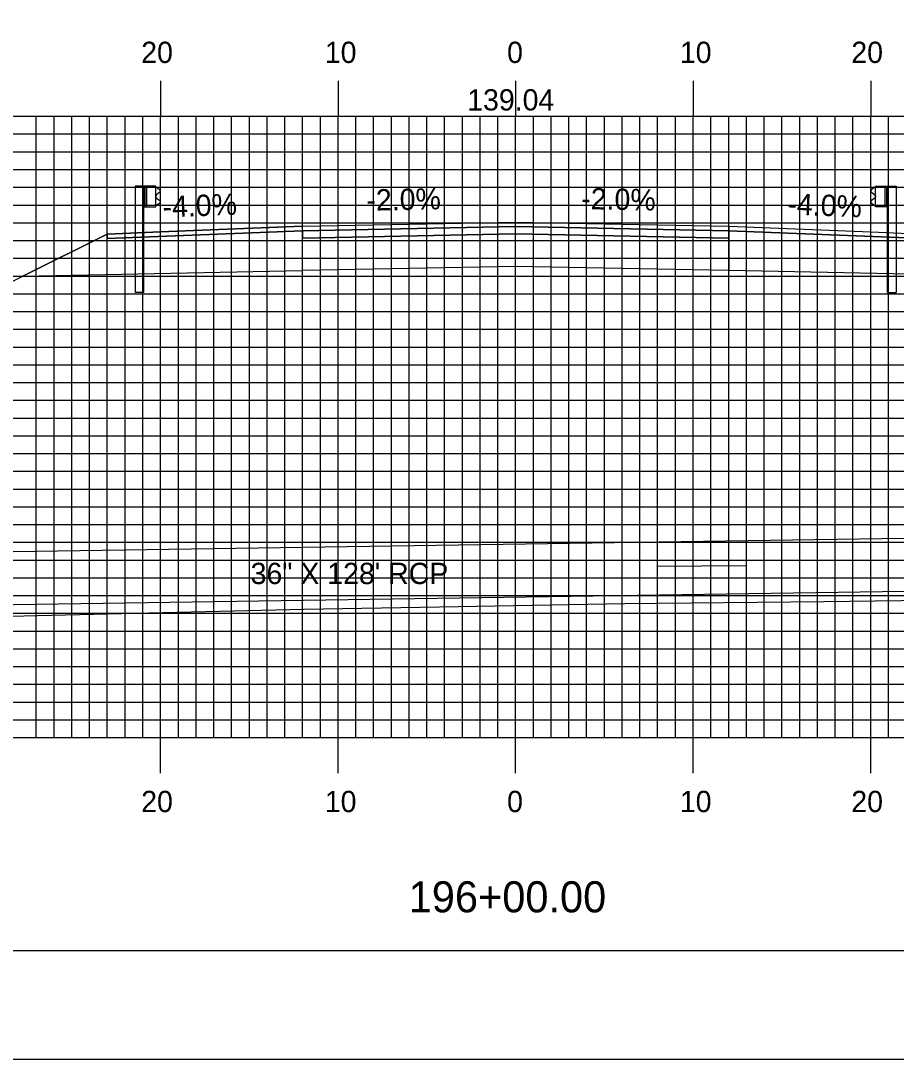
# Model space of a CAD drawing. Extents: x 1789730 to 1790074, y 442591 to 442811.
# Drawn here: x 1789868.3 to 1789917.6, y 442590.5 to 442649 of the extents above; entities that cross this region are included whole.
import ezdxf

# ---------------------------------------------------------------- set-up
doc = ezdxf.new("R2010")
doc.units = 0
for name, color, linetype in [('ANNOTATION', 7, 'Continuous'), ('BORDER', 7, 'Continuous'), ('D_Drainage_Culvert', 7, 'Continuous'), ('D_Drainage_Text', 7, 'Continuous'), ('D_Guardrail_Beam_Lt', 7, 'Continuous'), ('D_Guardrail_Beam_Rt', 7, 'Continuous'), ('D_Roadway_Centerline', 7, 'Continuous'), ('D_Roadway_Centerline_Text', 7, 'Continuous'), ('D_Roadway_Edge_Shoulder', 7, 'Continuous'), ('D_Roadway_Edge_TW', 7, 'Continuous'), ('D_Roadway_Pavement', 7, 'Continuous'), ('D_Roadway_SlopeLines', 7, 'Continuous'), ('D_Roadway_SubGrade', 7, 'Continuous'), ('H_V ANNOTATION', 7, 'Continuous'), ('MAJOR', 7, 'Continuous'), ('MINOR', 7, 'Continuous'), ('PLOT BOUNDARY', 7, 'Continuous'), ('S_Roadway_Centerline', 7, 'Continuous')]:
    doc.layers.add(name, color=color, linetype=linetype)

msp = doc.modelspace()

# ---------------------------------------------------------------- linework, layer by layer
at = {"layer": 'BORDER'}
msp.add_lwpolyline([(1789746.583, 442596.665), (1790066.583, 442596.665), (1790066.583, 442806.665), (1789746.583, 442806.665)], close=True, dxfattribs=at)
at = {"layer": 'D_Drainage_Culvert'}
msp.add_line((1789909.145, 442618.335), (1789904.158, 442618.294), dxfattribs=at)
msp.add_lwpolyline([(1789830.264, 442615.576), (1789830.219, 442618.576), (1789958.204, 442620.494), (1789958.249, 442617.494)], close=True, dxfattribs=at)
at = {"layer": 'D_Guardrail_Beam_Lt'}
for p, q in [((1789874.754, 442639.731), (1789874.754, 442633.731)), ((1789875.224, 442639.731), (1789874.754, 442639.731)), ((1789875.912, 442639.731), (1789875.224, 442639.731)), ((1789875.224, 442639.731), (1789875.224, 442638.564)), ((1789875.287, 442639.731), (1789875.287, 442638.564)), ((1789875.391, 442639.731), (1789875.391, 442638.564)), ((1789875.912, 442638.564), (1789875.912, 442639.731)), ((1789875.912, 442639.647), (1789875.986, 442639.633)), ((1789875.916, 442639.183), (1789875.916, 442639.112)), ((1789876.145, 442639.383), (1789875.95, 442639.247)), ((1789876.002, 442639.626), (1789876.145, 442639.526)), ((1789875.224, 442638.564), (1789875.912, 442638.564)), ((1789875.245, 442633.731), (1789875.245, 442638.564)), ((1789875.986, 442638.662), (1789875.912, 442638.647)), ((1789875.95, 442639.048), (1789876.145, 442638.912)), ((1789876.145, 442638.769), (1789876.002, 442638.669)), ((1789875.245, 442633.731), (1789874.754, 442633.731))]:
    msp.add_line(p, q, dxfattribs=at)
for centre, major_axis, start_param, end_param in [((1789875.995, 442639.183), (-0.0789, 0), 5.323254, 6.283185), ((1789875.995, 442639.112), (-0.0789, 0), 6.283185, 7.243116), ((1789875.978, 442639.592), (0.0417, 0), 0.959931, 1.376053), ((1789876.095, 442639.455), (0.0877, 0), 5.323254, 7.243116), ((1789875.978, 442638.703), (0.0417, 0), 4.907132, 5.323254), ((1789876.095, 442638.84), (0.0877, 0), 5.323254, 7.243116)]:
    msp.add_ellipse(centre, major_axis=major_axis, ratio=0.995501, start_param=start_param, end_param=end_param, dxfattribs=at)
at = {"layer": 'D_Guardrail_Beam_Rt'}
for p, q in [((1789916.454, 442639.647), (1789916.379, 442639.633)), ((1789916.454, 442639.731), (1789917.141, 442639.731)), ((1789916.454, 442638.564), (1789916.454, 442639.731)), ((1789916.974, 442639.731), (1789916.974, 442638.564)), ((1789917.079, 442639.731), (1789917.079, 442638.564)), ((1789917.141, 442639.731), (1789917.612, 442639.731)), ((1789917.141, 442639.731), (1789917.141, 442638.564)), ((1789917.612, 442639.731), (1789917.612, 442633.731)), ((1789916.364, 442639.626), (1789916.22, 442639.526)), ((1789916.22, 442639.383), (1789916.415, 442639.247)), ((1789916.449, 442639.183), (1789916.449, 442639.112)), ((1789916.415, 442639.048), (1789916.22, 442638.912)), ((1789916.22, 442638.769), (1789916.364, 442638.669)), ((1789916.379, 442638.662), (1789916.454, 442638.647)), ((1789917.141, 442638.564), (1789916.454, 442638.564)), ((1789917.12, 442633.731), (1789917.12, 442638.564)), ((1789917.12, 442633.731), (1789917.612, 442633.731))]:
    msp.add_line(p, q, dxfattribs=at)
for centre, major_axis, start_param, end_param in [((1789916.27, 442639.455), (-0.0877, 0), 5.323254, 7.243116), ((1789916.387, 442639.592), (-0.0417, 0), 4.907132, 5.323254), ((1789916.37, 442639.183), (0.0789, 0), 0, 0.959931), ((1789916.37, 442639.112), (0.0789, 0), 5.323254, 6.283185), ((1789916.27, 442638.84), (-0.0877, 0), 5.323254, 7.243116), ((1789916.387, 442638.703), (-0.0417, 0), 0.959931, 1.376053)]:
    msp.add_ellipse(centre, major_axis=major_axis, ratio=0.995501, start_param=start_param, end_param=end_param, dxfattribs=at)
at = {"layer": 'D_Roadway_Centerline'}
msp.add_lwpolyline([(1789830.28, 442615.576), (1789868.433, 442634.652), (1789873.183, 442637.027), (1789876.183, 442637.147), (1789884.183, 442637.467), (1789896.183, 442637.707), (1789908.183, 442637.467), (1789916.183, 442637.147), (1789919.183, 442637.027), (1789923.933, 442634.652), (1789958.249, 442617.494)], dxfattribs=at)
at = {"layer": 'D_Roadway_Edge_Shoulder'}
for points in [[(1789884.183, 442637.467), (1789876.183, 442637.147), (1789876.183, 442637.147), (1789873.183, 442637.027), (1789873.183, 442636.777), (1789884.183, 442637.217)], [(1789908.183, 442637.467), (1789916.183, 442637.147), (1789916.183, 442637.147), (1789919.183, 442637.027), (1789919.183, 442636.777), (1789908.183, 442637.217)]]:
    msp.add_lwpolyline(points, close=True, dxfattribs=at)
at = {"layer": 'D_Roadway_Edge_TW'}
msp.add_lwpolyline([(1789884.183, 442637.217), (1789884.183, 442637.467), (1789896.183, 442637.707), (1789908.183, 442637.467), (1789908.183, 442637.217), (1789896.183, 442637.457)], close=True, dxfattribs=at)
at = {"layer": 'D_Roadway_Pavement'}
msp.add_lwpolyline([(1789884.183, 442636.801), (1789884.183, 442637.217), (1789896.183, 442637.457), (1789908.183, 442637.217), (1789908.183, 442636.801), (1789896.183, 442637.041)], close=True, dxfattribs=at)
for points in [[(1789884.183, 442637.217), (1789884.183, 442636.801)], [(1789908.183, 442637.217), (1789908.183, 442636.801)]]:
    msp.add_lwpolyline(points, dxfattribs=at)
at = {"layer": 'D_Roadway_SlopeLines'}
msp.add_lwpolyline([(1789873.183, 442637.027), (1789830.28, 442615.576)], dxfattribs=at)
at = {"layer": 'D_Roadway_SubGrade'}
for points in [[(1789884.183, 442636.801), (1789884.183, 442637.217), (1789873.183, 442636.777), (1789873.183, 442637.027), (1789868.433, 442634.652), (1789884.183, 442634.967)], [(1789884.183, 442634.967), (1789884.183, 442637.217), (1789884.183, 442636.801), (1789896.183, 442637.041), (1789908.183, 442636.801), (1789908.183, 442637.217), (1789908.183, 442634.967), (1789896.183, 442635.207)], [(1789908.183, 442636.801), (1789908.183, 442637.217), (1789919.183, 442636.777), (1789919.183, 442637.027), (1789923.933, 442634.652), (1789908.183, 442634.967)]]:
    msp.add_lwpolyline(points, close=True, dxfattribs=at)
at = {"layer": 'MAJOR'}
for p, q in [((1789876.183, 442645.669), (1789876.183, 442643.665)), ((1789886.183, 442645.669), (1789886.183, 442643.665)), ((1789896.183, 442645.669), (1789896.183, 442643.665)), ((1789906.183, 442645.669), (1789906.183, 442643.665)), ((1789916.183, 442645.669), (1789916.183, 442643.665)), ((1789756.183, 442643.665), (1790036.183, 442643.665)), ((1789756.183, 442643.665), (1790036.183, 442643.665)), ((1789876.183, 442608.665), (1789876.183, 442643.665)), ((1789886.183, 442608.665), (1789886.183, 442643.665)), ((1789896.183, 442608.665), (1789896.183, 442643.665)), ((1789906.183, 442608.665), (1789906.183, 442643.665)), ((1789916.183, 442608.665), (1789916.183, 442643.665)), ((1789756.183, 442638.665), (1790036.183, 442638.665)), ((1789756.183, 442633.665), (1790036.183, 442633.665)), ((1789756.183, 442628.665), (1790036.183, 442628.665)), ((1789756.183, 442623.665), (1790036.183, 442623.665)), ((1789756.183, 442618.665), (1790036.183, 442618.665)), ((1789756.183, 442613.665), (1790036.183, 442613.665)), ((1789756.183, 442608.665), (1790036.183, 442608.665)), ((1789756.183, 442608.665), (1790036.183, 442608.665)), ((1789876.183, 442606.661), (1789876.183, 442608.665)), ((1789886.183, 442606.661), (1789886.183, 442608.665)), ((1789896.183, 442606.661), (1789896.183, 442608.665)), ((1789906.183, 442606.661), (1789906.183, 442608.665)), ((1789916.183, 442606.661), (1789916.183, 442608.665))]:
    msp.add_line(p, q, dxfattribs=at)
at = {"layer": 'MINOR'}
for p, q in [((1789869.183, 442608.665), (1789869.183, 442643.665)), ((1789870.183, 442608.665), (1789870.183, 442643.665)), ((1789871.183, 442608.665), (1789871.183, 442643.665)), ((1789872.183, 442608.665), (1789872.183, 442643.665)), ((1789873.183, 442608.665), (1789873.183, 442643.665)), ((1789874.183, 442608.665), (1789874.183, 442643.665)), ((1789875.183, 442608.665), (1789875.183, 442643.665)), ((1789877.183, 442608.665), (1789877.183, 442643.665)), ((1789878.183, 442608.665), (1789878.183, 442643.665)), ((1789879.183, 442608.665), (1789879.183, 442643.665)), ((1789880.183, 442608.665), (1789880.183, 442643.665)), ((1789881.183, 442608.665), (1789881.183, 442643.665)), ((1789882.183, 442608.665), (1789882.183, 442643.665)), ((1789883.183, 442608.665), (1789883.183, 442643.665)), ((1789884.183, 442608.665), (1789884.183, 442643.665)), ((1789885.183, 442608.665), (1789885.183, 442643.665)), ((1789887.183, 442608.665), (1789887.183, 442643.665)), ((1789888.183, 442608.665), (1789888.183, 442643.665)), ((1789889.183, 442608.665), (1789889.183, 442643.665)), ((1789890.183, 442608.665), (1789890.183, 442643.665)), ((1789891.183, 442608.665), (1789891.183, 442643.665)), ((1789892.183, 442608.665), (1789892.183, 442643.665)), ((1789893.183, 442608.665), (1789893.183, 442643.665)), ((1789894.183, 442608.665), (1789894.183, 442643.665)), ((1789895.183, 442608.665), (1789895.183, 442643.665)), ((1789897.183, 442608.665), (1789897.183, 442643.665)), ((1789898.183, 442608.665), (1789898.183, 442643.665)), ((1789899.183, 442608.665), (1789899.183, 442643.665)), ((1789900.183, 442608.665), (1789900.183, 442643.665)), ((1789901.183, 442608.665), (1789901.183, 442643.665)), ((1789902.183, 442608.665), (1789902.183, 442643.665)), ((1789903.183, 442608.665), (1789903.183, 442643.665)), ((1789904.183, 442608.665), (1789904.183, 442643.665)), ((1789905.183, 442608.665), (1789905.183, 442643.665)), ((1789907.183, 442608.665), (1789907.183, 442643.665)), ((1789908.183, 442608.665), (1789908.183, 442643.665)), ((1789909.183, 442608.665), (1789909.183, 442643.665)), ((1789910.183, 442608.665), (1789910.183, 442643.665)), ((1789911.183, 442608.665), (1789911.183, 442643.665)), ((1789912.183, 442608.665), (1789912.183, 442643.665)), ((1789913.183, 442608.665), (1789913.183, 442643.665)), ((1789914.183, 442608.665), (1789914.183, 442643.665)), ((1789915.183, 442608.665), (1789915.183, 442643.665)), ((1789917.183, 442608.665), (1789917.183, 442643.665)), ((1789756.183, 442642.665), (1790036.183, 442642.665)), ((1789756.183, 442641.665), (1790036.183, 442641.665)), ((1789756.183, 442640.665), (1790036.183, 442640.665)), ((1789756.183, 442639.665), (1790036.183, 442639.665)), ((1789756.183, 442637.665), (1790036.183, 442637.665)), ((1789756.183, 442636.665), (1790036.183, 442636.665)), ((1789756.183, 442635.665), (1790036.183, 442635.665)), ((1789756.183, 442634.665), (1790036.183, 442634.665)), ((1789756.183, 442632.665), (1790036.183, 442632.665)), ((1789756.183, 442631.665), (1790036.183, 442631.665)), ((1789756.183, 442630.665), (1790036.183, 442630.665)), ((1789756.183, 442629.665), (1790036.183, 442629.665)), ((1789756.183, 442627.665), (1790036.183, 442627.665)), ((1789756.183, 442626.665), (1790036.183, 442626.665)), ((1789756.183, 442625.665), (1790036.183, 442625.665)), ((1789756.183, 442624.665), (1790036.183, 442624.665)), ((1789756.183, 442622.665), (1790036.183, 442622.665)), ((1789756.183, 442621.665), (1790036.183, 442621.665)), ((1789756.183, 442620.665), (1790036.183, 442620.665)), ((1789756.183, 442619.665), (1790036.183, 442619.665)), ((1789756.183, 442617.665), (1790036.183, 442617.665)), ((1789756.183, 442616.665), (1790036.183, 442616.665)), ((1789756.183, 442615.665), (1790036.183, 442615.665)), ((1789756.183, 442614.665), (1790036.183, 442614.665)), ((1789756.183, 442612.665), (1790036.183, 442612.665)), ((1789756.183, 442611.665), (1790036.183, 442611.665)), ((1789756.183, 442610.665), (1790036.183, 442610.665)), ((1789756.183, 442609.665), (1790036.183, 442609.665))]:
    msp.add_line(p, q, dxfattribs=at)
at = {"layer": 'PLOT BOUNDARY'}
msp.add_lwpolyline([(1789730.396, 442590.547), (1790070.396, 442590.547), (1790070.396, 442810.547), (1789730.396, 442810.547)], close=True, dxfattribs=at)
at = {"layer": 'S_Roadway_Centerline'}
msp.add_lwpolyline([(1789866.101, 442615.468), (1789877.117, 442615.721), (1789884.245, 442615.898), (1789891.899, 442616.022), (1789902.339, 442616.224), (1789913.548, 442616.33), (1789920.798, 442616.417), (1789927.986, 442616.59), (1789939.227, 442616.951), (1789948.345, 442617.441), (1789967.66, 442617.545), (1789973.155, 442617.663), (1789975.475, 442617.594), (1789981.871, 442617.693), (1789993.214, 442617.848), (1789995.716, 442617.911), (1790007.509, 442618.287), (1790012.574, 442618.507), (1790017.23, 442618.665), (1790030.7, 442619.441), (1790036.183, 442619.425)], dxfattribs=at)

# ---------------------------------------------------------------- texts
at = {"layer": 'ANNOTATION'}
for s, rotation, p in [('-4.0%', 2.29061, (1789876.315, 442637.954)), ('-2.0%', 1.14576, (1789887.789, 442638.34)), ('-2.0%', 358.85424, (1789899.869, 442638.434)), ('-4.0%', 357.70939, (1789911.474, 442638.137))]:
    msp.add_text(s, height=1.2, rotation=rotation, dxfattribs=at).set_placement(p)
at = {"layer": 'D_Drainage_Text'}
msp.add_text('36" X 128\' RCP', height=1.2, dxfattribs=at).set_placement((1789881.255, 442617.312))
at = {"layer": 'D_Roadway_Centerline'}
for s, p in [('C', (1789896.177, 442637.707)), ('L', (1789896.183, 442637.7))]:
    msp.add_text(s, height=0.0146, dxfattribs=at).set_placement(p)
at = {"layer": 'D_Roadway_Centerline_Text'}
msp.add_text('139.04', height=1.2, dxfattribs=at).set_placement((1789893.454, 442643.988))
at = {"layer": 'H_V ANNOTATION'}
for s, height, p in [('20', 1.2, (1789875.091, 442646.665)), ('10', 1.2, (1789885.433, 442646.665)), ('0', 1.2, (1789895.701, 442646.665)), ('10', 1.2, (1789905.433, 442646.665)), ('20', 1.2, (1789915.091, 442646.665)), ('20', 1.2, (1789875.091, 442604.465)), ('10', 1.2, (1789885.433, 442604.465)), ('0', 1.2, (1789895.701, 442604.465)), ('10', 1.2, (1789905.433, 442604.465)), ('20', 1.2, (1789915.091, 442604.465)), ('196+00.00', 1.75, (1789890.159, 442598.821))]:
    msp.add_text(s, height=height, dxfattribs=at).set_placement(p)

doc.saveas('drawing.dxf')
